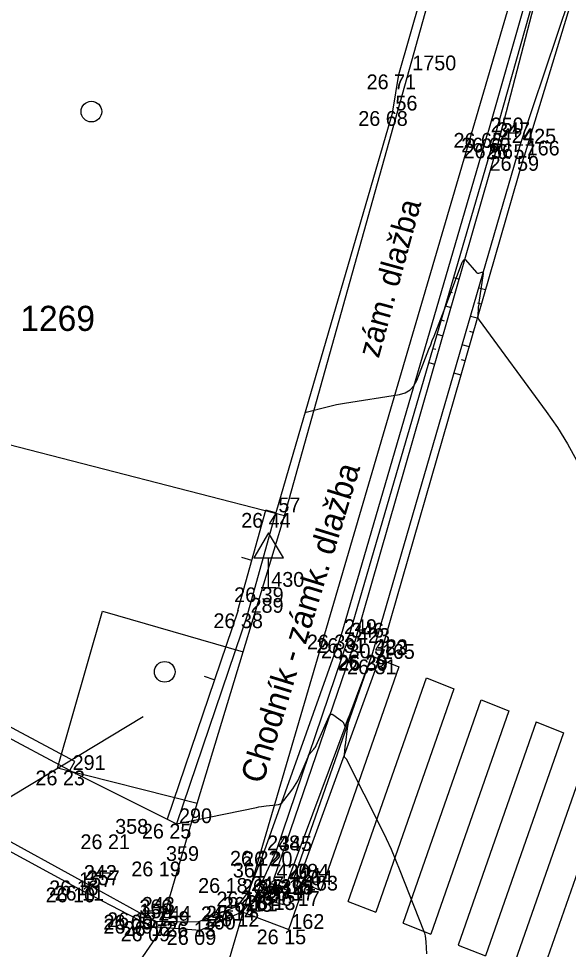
# Model space of a CAD drawing. Extents: x -702257 to -701487, y -1009871 to -1008841.
# Drawn here: x -701771.26 to -701761.96, y -1009374.37 to -1009358.61 of the extents above; entities that cross this region are included whole.
import ezdxf

# ---------------------------------------------------------------- set-up
doc = ezdxf.new("R2010")
doc.units = 0
for name, color, linetype in [('Ex_Minor Contours', 7, 'Continuous'), ('Z_body', 7, 'Continuous'), ('Z_body_cisla', 7, 'Continuous'), ('Z_body_vysky_redukovane', 7, 'Continuous'), ('Z_budova', 7, 'Continuous'), ('Z_dopravni_znacky', 7, 'Continuous'), ('Z_katastr_cisla_stavebni', 7, 'Continuous'), ('Z_katastr_hranice', 7, 'Continuous'), ('Z_katastr_parcelni_cislo_odkaz', 7, 'Continuous'), ('Z_katastr_znacky_budov', 7, 'Continuous'), ('Z_komunikace', 7, 'Continuous'), ('Z_obruba', 7, 'Continuous'), ('Z_ploty', 7, 'Continuous'), ('Z_ploty_znacky', 7, 'Continuous'), ('Z_popisy', 7, 'Continuous'), ('Z_rozhranni', 7, 'Continuous'), ('Z_site_kanalizace_znaky', 7, 'Continuous'), ('Z_technicke_srafy', 7, 'Continuous'), ('Z_vdz_prechod', 7, 'Continuous'), ('Z_vstupy', 7, 'Continuous'), ('Z_zlabek', 7, 'Continuous')]:
    doc.layers.add(name, color=color, linetype=linetype)

# ---------------------------------------------------------------- blocks, each defined once
blk = doc.blocks.new('POINT_DISPLAY')
blk.add_line((0, 0), (0, 0))
blk = doc.blocks.new('Z210_1')
blk.add_line((0, 0), (0, 0.175))
blk = doc.blocks.new('Z46260_1')
for p, q in [((0.125, 0.125), (-0.125, 0.125)), ((-0.125, 0.125), (-0.125, -0.125)), ((0.125, 0), (-0.125, 0)), ((0.125, -0.125), (0.125, 0.125)), ((-0.125, -0.125), (0.125, -0.125))]:
    blk.add_line(p, q)
blk = doc.blocks.new('Z527_1')
for p, q in [((0, 0.925), (-0.25, 0.5)), ((0.25, 0.5), (0, 0.925)), ((-0.25, 0.5), (0.25, 0.5)), ((0, 0), (0, 0.5)), ((-0.125, 0), (0.125, 0))]:
    blk.add_line(p, q)
blk = doc.blocks.new('Z46260_2')
for p, q in [((0.125, 0.125), (-0.125, 0.125)), ((-0.125, 0.125), (-0.125, -0.125)), ((0.125, 0), (-0.125, 0)), ((0.125, -0.125), (0.125, 0.125)), ((-0.125, -0.125), (0.125, -0.125))]:
    blk.add_line(p, q)
blk = doc.blocks.new('Z527_2')
for p, q in [((0, 0.925), (-0.25, 0.5)), ((0.25, 0.5), (0, 0.925)), ((-0.25, 0.5), (0.25, 0.5)), ((0, 0), (0, 0.5)), ((-0.125, 0), (0.125, 0))]:
    blk.add_line(p, q)

msp = doc.modelspace()

# ---------------------------------------------------------------- linework, layer by layer
at = {"layer": 'Ex_Minor Contours'}
for points in [[(-701766.415, -1009365.28), (-701766.017, -1009365.177), (-701765.95, -1009365.161), (-701765.884, -1009365.146), (-701765.816, -1009365.133), (-701765.749, -1009365.122), (-701764.817, -1009364.975), (-701764.718, -1009364.948), (-701764.637, -1009364.899), (-701764.572, -1009364.83), (-701764.524, -1009364.74), (-701764.346, -1009364.28), (-701764.318, -1009364.207), (-701764.289, -1009364.134), (-701764.261, -1009364.061), (-701764.232, -1009363.988), (-701764.119, -1009363.697), (-701764.09, -1009363.624), (-701764.062, -1009363.551), (-701764.034, -1009363.477), (-701764.007, -1009363.404), (-701763.764, -1009362.756), (-701763.76, -1009362.748), (-701763.756, -1009362.74), (-701763.751, -1009362.732), (-701763.746, -1009362.725), (-701763.722, -1009362.696), (-701763.717, -1009362.691), (-701763.711, -1009362.689), (-701763.705, -1009362.691), (-701763.699, -1009362.696), (-701763.516, -1009362.911), (-701763.507, -1009362.919), (-701763.496, -1009362.924), (-701763.485, -1009362.925), (-701763.473, -1009362.923), (-701763.423, -1009362.908), (-701763.412, -1009362.906), (-701763.405, -1009362.908), (-701763.401, -1009362.915), (-701763.401, -1009362.926), (-701763.474, -1009363.421), (-701763.477, -1009363.446), (-701763.48, -1009363.472), (-701763.483, -1009363.498), (-701763.485, -1009363.524), (-701763.493, -1009363.627), (-701763.493, -1009363.652), (-701763.489, -1009363.676), (-701763.48, -1009363.699), (-701763.467, -1009363.72), (-701762.333, -1009365.266), (-701762.146, -1009365.535), (-701761.974, -1009365.812), (-701761.816, -1009366.098)], [(-701768.59, -1009372.24), (-701767.234, -1009371.963), (-701767.193, -1009371.955), (-701767.152, -1009371.949), (-701767.111, -1009371.943), (-701767.07, -1009371.939), (-701766.904, -1009371.923), (-701766.865, -1009371.916), (-701766.83, -1009371.901), (-701766.798, -1009371.879), (-701766.771, -1009371.849), (-701766.623, -1009371.651), (-701766.591, -1009371.606), (-701766.562, -1009371.56), (-701766.536, -1009371.512), (-701766.513, -1009371.462), (-701766.361, -1009371.106), (-701766.353, -1009371.088), (-701766.343, -1009371.071), (-701766.332, -1009371.055), (-701766.319, -1009371.039), (-701766.266, -1009370.98), (-701766.254, -1009370.964), (-701766.243, -1009370.948), (-701766.233, -1009370.931), (-701766.224, -1009370.914), (-701766.006, -1009370.421), (-701765.991, -1009370.398), (-701765.974, -1009370.387), (-701765.953, -1009370.388), (-701765.929, -1009370.401), (-701765.795, -1009370.497), (-701765.786, -1009370.505), (-701765.778, -1009370.514), (-701765.771, -1009370.524), (-701765.766, -1009370.535), (-701765.746, -1009370.58), (-701765.742, -1009370.589), (-701765.737, -1009370.592), (-701765.733, -1009370.589), (-701765.728, -1009370.58), (-701765.676, -1009370.445), (-701765.671, -1009370.432), (-701765.669, -1009370.429), (-701765.668, -1009370.433), (-701765.67, -1009370.446), (-701765.683, -1009370.515), (-701765.686, -1009370.532), (-701765.689, -1009370.549), (-701765.691, -1009370.567), (-701765.694, -1009370.584), (-701765.735, -1009370.91), (-701765.738, -1009370.929), (-701765.74, -1009370.948), (-701765.742, -1009370.967), (-701765.744, -1009370.986), (-701765.754, -1009371.088), (-701765.754, -1009371.094), (-701765.753, -1009371.1), (-701765.75, -1009371.106), (-701765.746, -1009371.111), (-701765.727, -1009371.13), (-701765.722, -1009371.135), (-701765.718, -1009371.141), (-701765.714, -1009371.146), (-701765.711, -1009371.152), (-701765.129, -1009372.313), (-701765.042, -1009372.49), (-701764.96, -1009372.67), (-701764.882, -1009372.851), (-701764.808, -1009373.034), (-701764.411, -1009374.045), (-701764.395, -1009374.092), (-701764.383, -1009374.139), (-701764.374, -1009374.187), (-701764.37, -1009374.237), (-701764.361, -1009374.442)]]:
    msp.add_lwpolyline(points, dxfattribs=at)
at = {"layer": 'Z_body'}
msp.add_line((-701762.23, -1009356.72), (-701763.32, -1009360.55), dxfattribs=at)
at = {"layer": 'Z_budova'}
for p, q in [((-701764.83, -1009359.56), (-701762, -1009349.65)), ((-701764.93, -1009360.18), (-701764.83, -1009359.56)), ((-701764.93, -1009360.18), (-701766.91, -1009366.98)), ((-701764.93, -1009360.18), (-701766.91, -1009366.98)), ((-701766.91, -1009366.98), (-701767.079, -1009366.933))]:
    msp.add_line(p, q, dxfattribs=at)
at = {"layer": 'Z_katastr_hranice'}
for p, q in [((-701767.72, -1009374.62), (-701754.56, -1009329.71)), ((-701766.76, -1009367.03), (-701764.34, -1009358.38)), ((-701766.76, -1009367.03), (-701771.79, -1009365.73)), ((-701767.46, -1009369.33), (-701766.76, -1009367.03)), ((-701770.6, -1009371.3), (-701769.84, -1009368.64)), ((-701769.84, -1009368.64), (-701767.46, -1009369.33)), ((-701768.24, -1009371.9), (-701767.46, -1009369.33)), ((-701768.24, -1009371.9), (-701770.6, -1009371.3)), ((-701768.88, -1009374.09), (-701768.24, -1009371.9)), ((-701773.73, -1009381.12), (-701768.88, -1009374.09))]:
    msp.add_line(p, q, dxfattribs=at)
at = {"layer": 'Z_katastr_parcelni_cislo_odkaz'}
msp.add_line((-701769.15, -1009370.43), (-701771.93, -1009372.11), dxfattribs=at)
at = {"layer": 'Z_katastr_znacky_budov'}
for centre in [(-701770.027, -1009360.189), (-701768.787, -1009369.669)]:
    msp.add_circle(centre, 0.175, dxfattribs=at)
at = {"layer": 'Z_komunikace'}
for p, q in [((-701765.16, -1009369.46), (-701762.71, -1009360.94)), ((-701777.27, -1009369.5), (-701770.28, -1009373.32)), ((-701766.55, -1009373.29), (-701765.16, -1009369.46)), ((-701770.28, -1009373.32), (-701769.26, -1009373.85)), ((-701766.46, -1009373.38), (-701766.55, -1009373.29)), ((-701766.69, -1009374.03), (-701766.46, -1009373.38)), ((-701768.19, -1009374.04), (-701767.48, -1009373.73)), ((-701767.48, -1009373.73), (-701766.69, -1009374.03)), ((-701769.26, -1009373.85), (-701768.97, -1009373.98)), ((-701768.97, -1009373.98), (-701768.19, -1009374.04))]:
    msp.add_line(p, q, dxfattribs=at)
at = {"layer": 'Z_obruba'}
for p, q in [((-701765.8, -1009369.04), (-701763.32, -1009360.55)), ((-701767.1, -1009372.7), (-701765.8, -1009369.04)), ((-701777.17, -1009369.38), (-701770.2, -1009373.2)), ((-701767.37, -1009373.39), (-701767.1, -1009372.7)), ((-701770.2, -1009373.2), (-701769.22, -1009373.74)), ((-701767.55, -1009373.63), (-701767.37, -1009373.39)), ((-701768.22, -1009373.9), (-701767.55, -1009373.63)), ((-701769.22, -1009373.74), (-701768.94, -1009373.89)), ((-701768.94, -1009373.89), (-701768.22, -1009373.9))]:
    msp.add_line(p, q, dxfattribs=at)
at = {"layer": 'Z_ploty'}
for p, q in [((-701767.549, -1009368.633), (-701767.079, -1009366.933)), ((-701767.38, -1009368.68), (-701766.91, -1009366.98)), ((-701767.38, -1009368.68), (-701766.91, -1009366.98)), ((-701770.308, -1009371.186), (-701777.388, -1009367.416)), ((-701770.39, -1009371.34), (-701777.47, -1009367.57)), ((-701770.39, -1009371.34), (-701777.47, -1009367.57)), ((-701767.546, -1009368.624), (-701768.748, -1009372.161)), ((-701767.38, -1009368.68), (-701768.59, -1009372.24)), ((-701767.38, -1009368.68), (-701768.59, -1009372.24)), ((-701770.39, -1009371.34), (-701770.308, -1009371.186))]:
    msp.add_line(p, q, dxfattribs=at)
at = {"layer": 'Z_rozhranni'}
for p, q in [((-701763.21, -1009360.63), (-701762.11, -1009356.75)), ((-701765.68, -1009369.1), (-701763.21, -1009360.63)), ((-701765.68, -1009369.1), (-701763.21, -1009360.63)), ((-701766.9, -1009372.71), (-701765.68, -1009369.1)), ((-701766.9, -1009372.71), (-701765.68, -1009369.1)), ((-701767.26, -1009373.48), (-701766.9, -1009372.71)), ((-701767.26, -1009373.48), (-701766.9, -1009372.71)), ((-701767.26, -1009373.48), (-701767.48, -1009373.73)), ((-701767.26, -1009373.48), (-701767.48, -1009373.73))]:
    msp.add_line(p, q, dxfattribs=at)
at = {"layer": 'Z_technicke_srafy'}
for p, q in [((-701763.9, -1009362.995), (-701763.808, -1009363.022)), ((-701763.97, -1009363.235), (-701763.924, -1009363.249)), ((-701763.362, -1009363.207), (-701763.477, -1009363.174)), ((-701764.04, -1009363.475), (-701763.946, -1009363.503)), ((-701763.431, -1009363.447), (-701763.489, -1009363.43)), ((-701764.11, -1009363.715), (-701764.063, -1009363.729)), ((-701763.5, -1009363.687), (-701763.616, -1009363.654)), ((-701764.18, -1009363.955), (-701764.084, -1009363.983)), ((-701763.569, -1009363.927), (-701763.628, -1009363.911)), ((-701764.25, -1009364.196), (-701764.202, -1009364.21)), ((-701763.638, -1009364.168), (-701763.756, -1009364.134)), ((-701764.32, -1009364.436), (-701764.222, -1009364.464)), ((-701763.707, -1009364.408), (-701763.766, -1009364.391)), ((-701763.776, -1009364.648), (-701763.895, -1009364.614))]:
    msp.add_line(p, q, dxfattribs=at)
at = {"layer": 'Z_vdz_prechod'}
for p, q in [((-701765.29, -1009369.4), (-701766.61, -1009373.18)), ((-701765.29, -1009369.4), (-701766.61, -1009373.18)), ((-701765.29, -1009369.4), (-701764.826, -1009369.585)), ((-701765.29, -1009369.4), (-701764.826, -1009369.585)), ((-701764.826, -1009369.585), (-701766.147, -1009373.37)), ((-701765.683, -1009373.554), (-701764.362, -1009369.771)), ((-701764.362, -1009369.771), (-701763.897, -1009369.957)), ((-701763.897, -1009369.957), (-701765.218, -1009373.739)), ((-701764.753, -1009373.924), (-701763.433, -1009370.143)), ((-701763.433, -1009370.143), (-701762.969, -1009370.329)), ((-701762.969, -1009370.329), (-701764.289, -1009374.109)), ((-701762.505, -1009370.515), (-701763.824, -1009374.293)), ((-701762.505, -1009370.515), (-701762.041, -1009370.701)), ((-701762.041, -1009370.701), (-701763.36, -1009374.478)), ((-701761.577, -1009370.887), (-701762.895, -1009374.663)), ((-701762.43, -1009374.848), (-701761.104, -1009371.05)), ((-701766.61, -1009373.18), (-701766.147, -1009373.37)), ((-701765.683, -1009373.554), (-701765.218, -1009373.739)), ((-701764.753, -1009373.924), (-701764.289, -1009374.109)), ((-701763.824, -1009374.293), (-701763.36, -1009374.478))]:
    msp.add_line(p, q, dxfattribs=at)
at = {"layer": 'Z_vstupy'}
msp.add_line((-701770.39, -1009371.34), (-701768.59, -1009372.24), dxfattribs=at)
msp.add_line((-701770.39, -1009371.34), (-701768.59, -1009372.24), dxfattribs=at)
at = {"layer": 'Z_zlabek'}
for p, q in [((-701763.15, -1009360.73), (-701762.11, -1009356.75)), ((-701762.77, -1009360.74), (-701761.48, -1009356.91)), ((-701761.48, -1009356.91), (-701762.71, -1009360.94)), ((-701765.58, -1009369.19), (-701763.15, -1009360.73)), ((-701765.58, -1009369.19), (-701763.15, -1009360.73)), ((-701765.28, -1009369.38), (-701762.77, -1009360.74)), ((-701765.28, -1009369.38), (-701762.77, -1009360.74)), ((-701766.94, -1009373.18), (-701765.58, -1009369.19)), ((-701766.94, -1009373.18), (-701765.58, -1009369.19)), ((-701766.72, -1009373.25), (-701765.28, -1009369.38)), ((-701766.72, -1009373.25), (-701765.28, -1009369.38)), ((-701766.72, -1009373.25), (-701766.94, -1009373.18)), ((-701766.72, -1009373.25), (-701766.94, -1009373.18))]:
    msp.add_line(p, q, dxfattribs=at)

# ---------------------------------------------------------------- block references
at = {"layer": 'Z_body'}
for p in [(-701764.83, -1009359.56), (-701764.93, -1009360.18), (-701763.32, -1009360.55), (-701763.21, -1009360.63), (-701763.15, -1009360.73), (-701762.77, -1009360.74), (-701762.71, -1009360.94), (-701766.91, -1009366.98), (-701767.03, -1009368.24), (-701767.38, -1009368.68), (-701765.8, -1009369.04), (-701765.68, -1009369.1), (-701765.58, -1009369.19), (-701765.28, -1009369.38), (-701765.29, -1009369.4), (-701765.16, -1009369.46), (-701770.39, -1009371.34), (-701768.59, -1009372.24), (-701769.67, -1009372.42), (-701767.1, -1009372.7), (-701766.9, -1009372.71), (-701768.81, -1009372.88), (-701767.68, -1009373.16), (-701770.28, -1009373.32), (-701770.2, -1009373.2), (-701770.15, -1009373.29), (-701766.94, -1009373.18), (-701766.72, -1009373.25), (-701766.61, -1009373.18), (-701766.55, -1009373.29), (-701767.37, -1009373.39), (-701767.26, -1009373.48), (-701766.87, -1009373.45), (-701766.46, -1009373.38), (-701767.55, -1009373.63), (-701769.26, -1009373.78), (-701769.22, -1009373.74), (-701767.48, -1009373.73), (-701769.26, -1009373.85), (-701768.94, -1009373.89), (-701768.22, -1009373.9), (-701768.97, -1009373.98), (-701768.19, -1009374.04), (-701766.69, -1009374.03)]:
    msp.add_blockref('POINT_DISPLAY', p, dxfattribs=at)
at = {"layer": 'Z_dopravni_znacky'}
for name in ['Z527_1', 'Z527_2']:
    msp.add_blockref(name, (-701767.03, -1009368.24), dxfattribs=at)
at = {"layer": 'Z_ploty_znacky'}
for p, rotation in [((-701767.314, -1009367.783), 74.5), ((-701767.948, -1009369.807), 71.2)]:
    msp.add_blockref('Z210_1', p, dxfattribs=dict(at, rotation=rotation))
at = {"layer": 'Z_site_kanalizace_znaky', "rotation": 73.8}
for name in ['Z46260_1', 'Z46260_2']:
    msp.add_blockref(name, (-701766.87, -1009373.45), dxfattribs=at)

# ---------------------------------------------------------------- texts
at = {"layer": 'Z_body_cisla'}
for s, p in [('1750', (-701764.6, -1009359.49)), ('56', (-701764.885, -1009360.17)), ('250', (-701763.275, -1009360.54)), ('347', (-701763.165, -1009360.62)), ('424', (-701763.105, -1009360.72)), ('425', (-701762.725, -1009360.73)), ('166', (-701762.665, -1009360.93)), ('57', (-701766.865, -1009366.97)), ('430', (-701766.985, -1009368.23)), ('289', (-701767.335, -1009368.67)), ('249', (-701765.755, -1009369.03)), ('346', (-701765.635, -1009369.09)), ('423', (-701765.535, -1009369.18)), ('383', (-701765.245, -1009369.39)), ('422', (-701765.235, -1009369.37)), ('165', (-701765.115, -1009369.45)), ('291', (-701770.345, -1009371.33)), ('290', (-701768.545, -1009372.23)), ('358', (-701769.625, -1009372.41)), ('248', (-701767.055, -1009372.69)), ('345', (-701766.855, -1009372.7)), ('359', (-701768.765, -1009372.87)), ('242', (-701770.155, -1009373.19)), ('361', (-701767.635, -1009373.15)), ('420', (-701766.895, -1009373.17)), ('421', (-701766.675, -1009373.24)), ('384', (-701766.565, -1009373.17)), ('157', (-701770.235, -1009373.31)), ('357', (-701770.105, -1009373.28)), ('247', (-701767.325, -1009373.38)), ('164', (-701766.505, -1009373.28)), ('163', (-701766.415, -1009373.37)), ('344', (-701767.215, -1009373.47)), ('398', (-701766.825, -1009373.44)), ('243', (-701769.175, -1009373.73)), ('246', (-701767.505, -1009373.62)), ('161', (-701767.435, -1009373.72)), ('360', (-701769.215, -1009373.77)), ('158', (-701769.215, -1009373.84)), ('244', (-701768.895, -1009373.88)), ('245', (-701768.175, -1009373.89)), ('159', (-701768.925, -1009373.97)), ('160', (-701768.145, -1009374.03)), ('162', (-701766.645, -1009374.02))]:
    msp.add_text(s, height=0.25, dxfattribs=at).set_placement(p)
at = {"layer": 'Z_body_vysky_redukovane'}
for s, p in [('26 71', (-701765.372, -1009359.81)), ('26 68', (-701765.513, -1009360.43)), ('26 65', (-701763.903, -1009360.8)), ('26 60', (-701763.773, -1009360.88)), ('26 56', (-701763.733, -1009360.98)), ('26 57', (-701763.353, -1009360.99)), ('26 59', (-701763.293, -1009361.19)), ('26 44', (-701767.493, -1009367.23)), ('26 39', (-701767.613, -1009368.49)), ('26 38', (-701767.963, -1009368.93)), ('26 36', (-701766.383, -1009369.29)), ('26 31', (-701766.222, -1009369.35)), ('26 30', (-701766.143, -1009369.44)), ('26 29', (-701765.863, -1009369.63)), ('26 30', (-701765.853, -1009369.65)), ('26 31', (-701765.702, -1009369.71)), ('26 23', (-701770.973, -1009371.59)), ('26 25', (-701769.173, -1009372.49)), ('26 21', (-701770.212, -1009372.67)), ('26 22', (-701767.683, -1009372.95)), ('26 20', (-701767.463, -1009372.96)), ('26 19', (-701769.352, -1009373.13)), ('26 18', (-701768.222, -1009373.41)), ('26 13', (-701767.482, -1009373.43)), ('26 16', (-701767.152, -1009373.43)), ('26 10', (-701770.801, -1009373.57)), ('26 16', (-701770.742, -1009373.45)), ('26 11', (-701770.65, -1009373.54)), ('26 14', (-701767.262, -1009373.5)), ('26 17', (-701767.092, -1009373.54)), ('26 17', (-701767.912, -1009373.64)), ('26 13', (-701767.802, -1009373.73)), ('26 13', (-701767.412, -1009373.7)), ('26 17', (-701767.002, -1009373.63)), ('26 14', (-701768.092, -1009373.88)), ('26 09', (-701769.823, -1009374.03)), ('26 13', (-701769.762, -1009373.99)), ('26 12', (-701768.022, -1009373.98)), ('26 09', (-701769.823, -1009374.1)), ('26 12', (-701769.482, -1009374.14)), ('26 13', (-701768.762, -1009374.15)), ('26 09', (-701769.533, -1009374.23)), ('26 09', (-701768.752, -1009374.29)), ('26 15', (-701767.232, -1009374.28))]:
    msp.add_text(s, height=0.25, dxfattribs=at).set_placement(p)
at = {"layer": 'Z_katastr_cisla_stavebni'}
msp.add_text('1269', height=0.425, dxfattribs=at).set_placement((-701771.23, -1009363.9))
at = {"layer": 'Z_popisy'}
for s, height, rotation, p in [('zám. dlažba', 0.38, 74.7, (-701765.168, -1009364.375)), ('Chodník - zámk. dlažba', 0.4, 72.9, (-701767.13, -1009371.581))]:
    msp.add_text(s, height=height, rotation=rotation, dxfattribs=at).set_placement(p)

doc.saveas('drawing.dxf')
